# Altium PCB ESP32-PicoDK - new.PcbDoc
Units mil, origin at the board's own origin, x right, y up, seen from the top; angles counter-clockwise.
Board outline 2080 x 1506 mil, 2 copper layers (Top1, Bottom2), stack 40.202 mil thick; 47 components, 68 nets, 274 pads, 137 vias.
Unrouted connection lines stored in the file: 1.
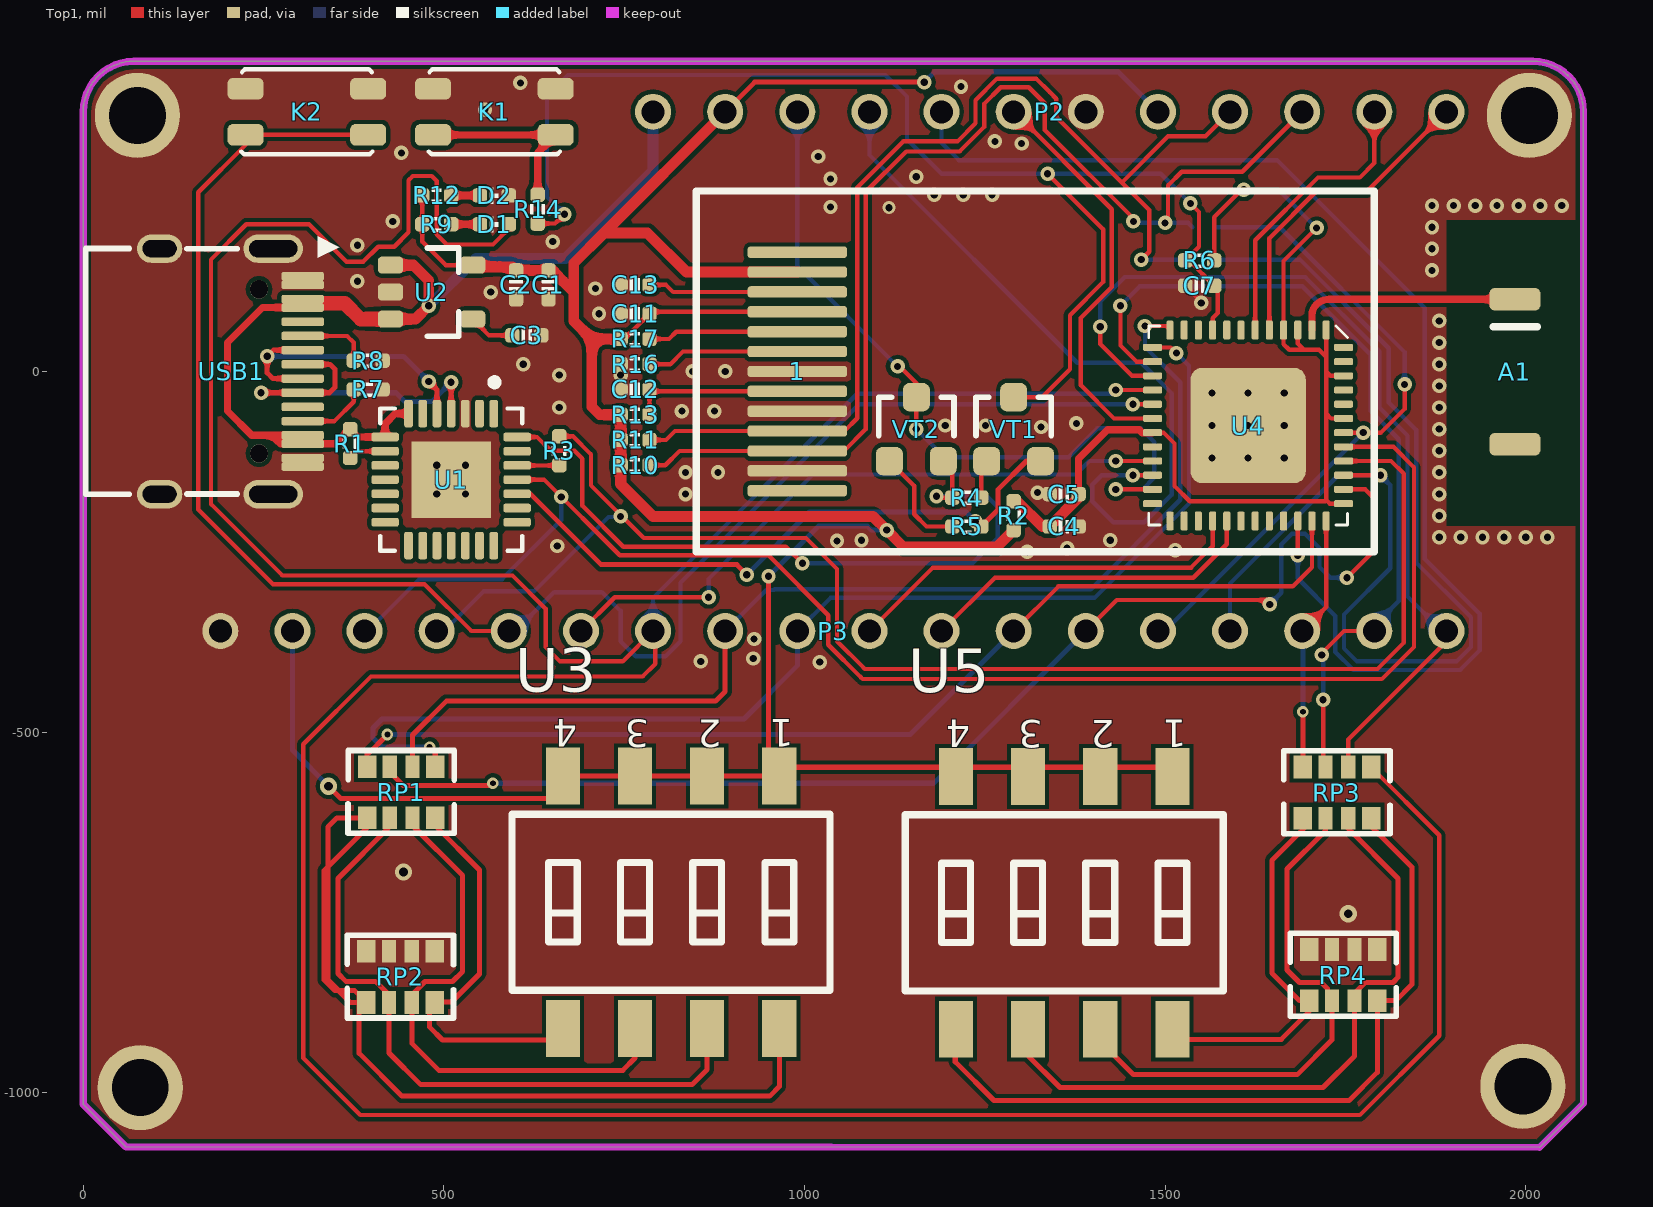
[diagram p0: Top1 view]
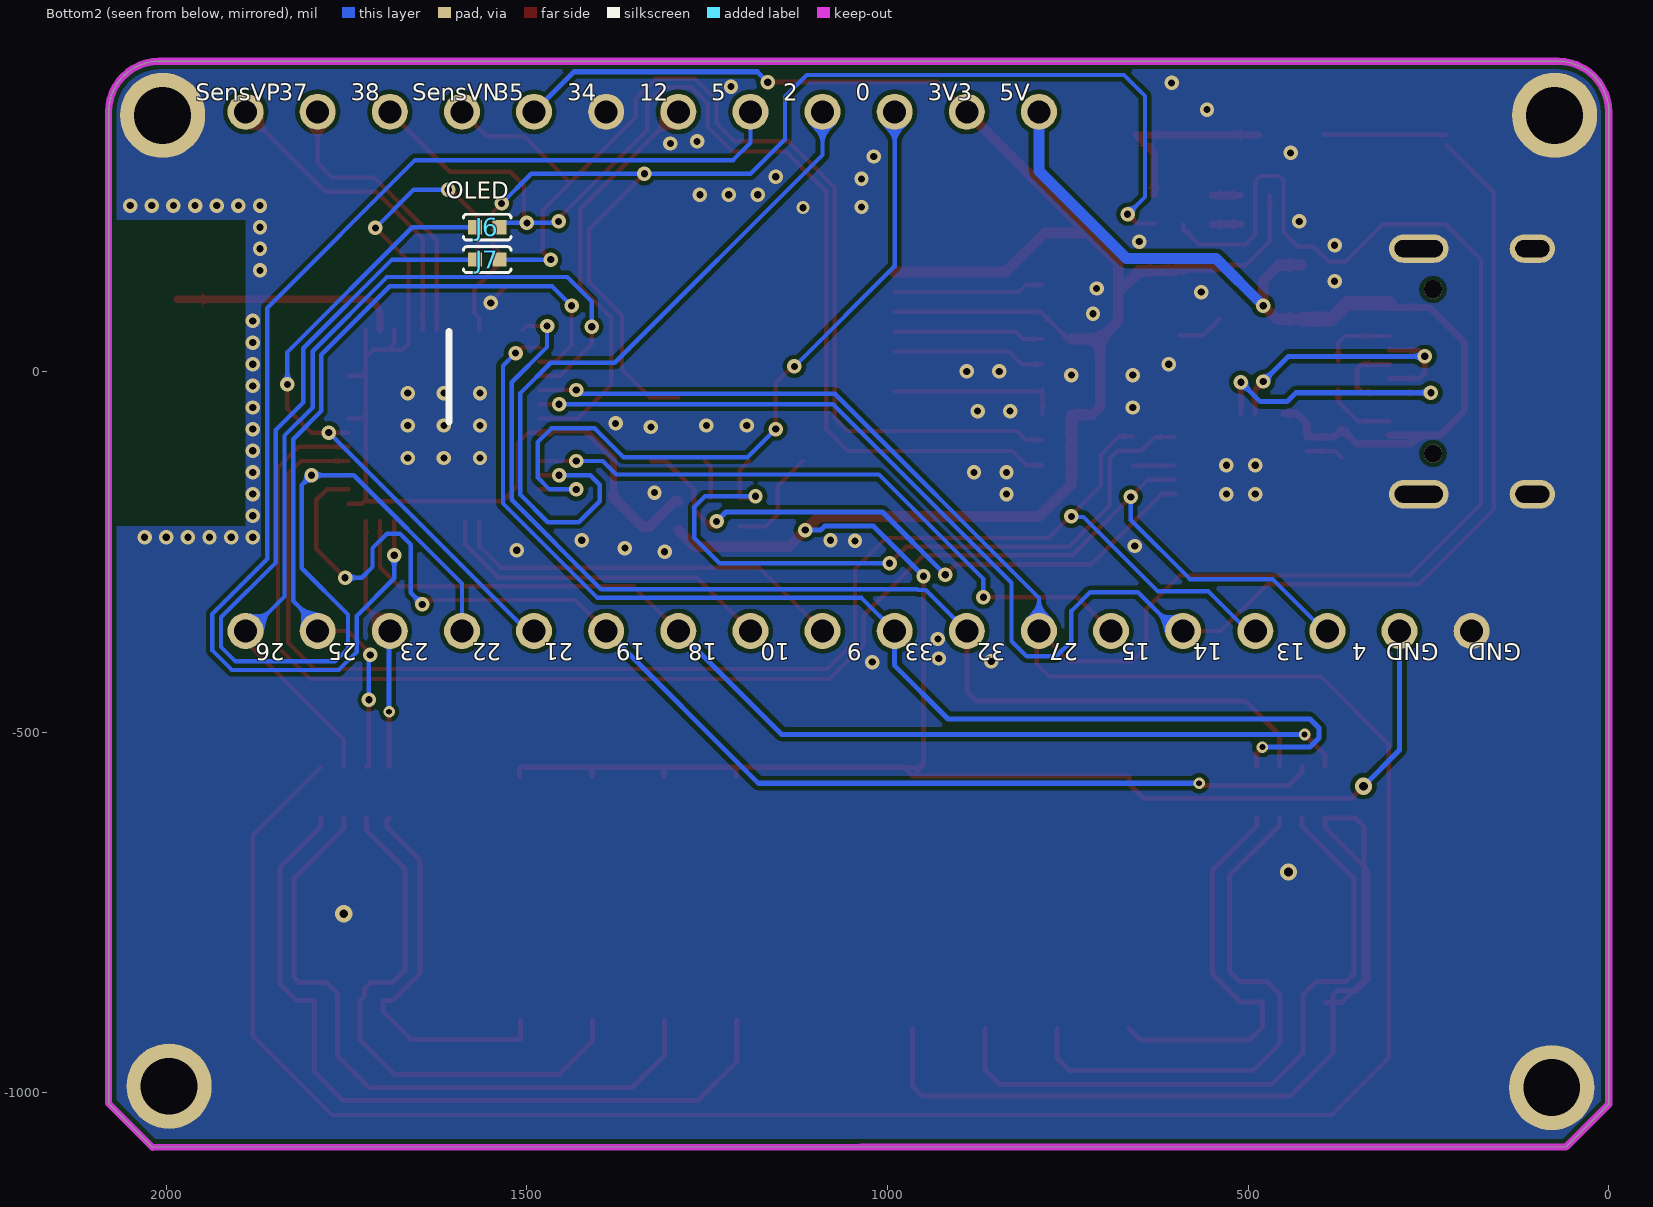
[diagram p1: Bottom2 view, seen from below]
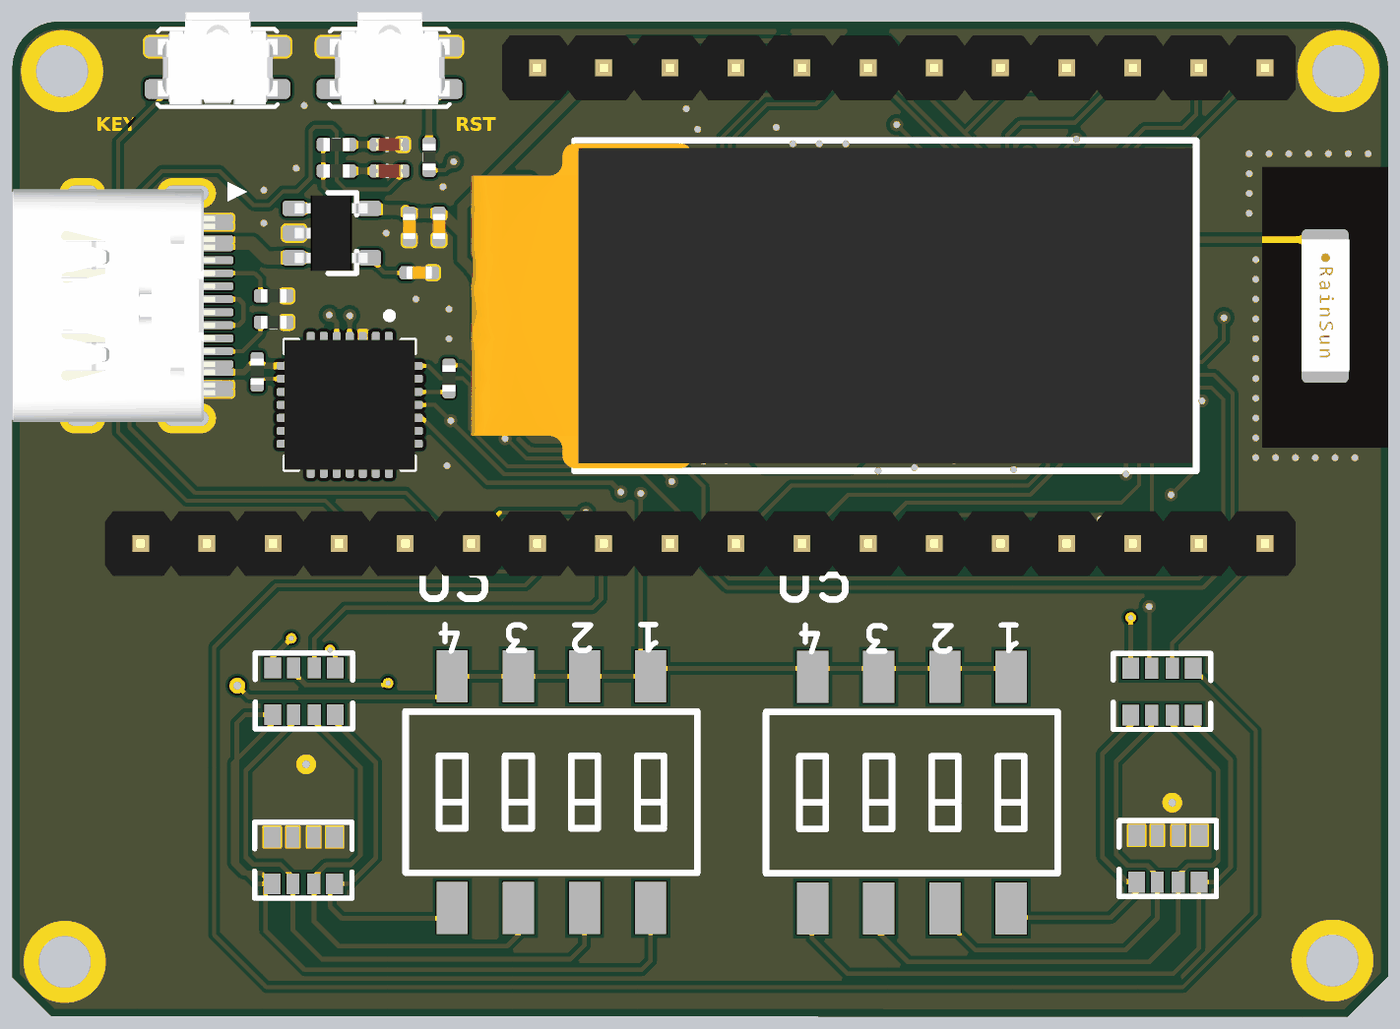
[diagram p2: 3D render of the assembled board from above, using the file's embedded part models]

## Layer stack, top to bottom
Top Solder: solder mask 0.4, Solder Resist, Dk 3.5
Top1: signal copper 1.4
Dielectric 1: core 37.4016, FR-4, Dk 4.2
Bottom2: signal copper 1.4
Bottom Solder: solder mask 0.4, Solder Resist, Dk 3.5

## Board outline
0,-1016 59,-1075 2019,-1076 2080,-1015 2080,360 ccw(c2010,360) 2010,430 70,430 ccw(c70,360) 0,360

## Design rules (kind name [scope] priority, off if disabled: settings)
Clearance [All] p1: gap=6 ignorepadtopadclearanceinfootprint=FALSE
ComponentClearance [All] p1: gap=0 collisioncheckmode=3 verticalgap=0 showdistances=FALSE
DiffPairsRouting [All] p1: maxlimit=9 minlimit=9 mostfreqgap=9 toplayer_minwidth=4 toplayer_maxwidth=4 toplayer_prefwidth=4 bottomlayer_minwidth=4 bottomlayer_maxwidth=4 bottomlayer_prefwidth=4 maxuncoupledlength=500
FanoutControl Fanout_BGA [All] p1: bgadir=Out bgaviamode=Centered fanoutstyle=Auto fanoutdirection=Alternating viagrid=1 // Fanout_BGA (Default Rule)
HoleSize [All] p1: absolutevalues=TRUE maxlimit=10000 minlimit=8 maxpercent=80.000 minpercent=20.000
MinimumSolderMaskSliver [All] p1 off: minsoldermaskwidth=2
PlaneClearance [All] p1: clearance=8
PlaneConnect [All] p1: planeconnectstyle=Direct reliefexpansion=20 reliefentries=4 reliefconductorwidth=10 reliefairgap=10
PolygonConnect [All] p1: connectstyle=Direct reliefconductorwidth=10 reliefentries=4 polygonreliefangle="90 Angle" airgapwidth=10
RoutingVias [All] p1: holewidth=8 width=16 viastyle="Through Hole" minholewidth=6 minwidth=12 maxholewidth=28 maxwidth=50
SilkToBoardRegionClearance [All] p1 off:
SilkToSilkClearance [All] p1: silktosilkclearance=0
SilkToSolderMaskClearance [IsPad] p1: minsilkscreentomaskgap=0 clearancetoexposedcopper=TRUE
SolderMaskExpansion [All] p1: expansion=3
Width [All] p1: maxlimit=10000 minlimit=6 preferedwidth=7
20 further rules are at their usual default settings.

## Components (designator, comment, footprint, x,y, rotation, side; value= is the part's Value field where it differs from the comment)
1 "OLED-12880" OLED-12880 990,0 r180 top locked
A1 "RAINSUN" ANT-Rainsun-AN5120 1985,0 r270 top
C1 "0.1uF" CAP_0402 645,120 r90 top value=0.1u
C2 "10uF" CAP_0402 600,120 r90 top value=0.1u
C3 "10nF" CAP_0402 615,50 r180 top value=0.1u
C4 "10uF" CAP_0402 1360,-215 r180 top value=0.1u
C5 "0.1uF" CAP_0402 1360,-170 r0 top value=0.1u
C7 "0.1uF" CAP_0402 1548,118.89 r180 top value=0.1u
C11 "10uF" CAP_0402 765,80 r0 top value=0.1u
C12 "10uF" CAP_0402 765,-25 r0 top value=0.1u
C13 "10uF" CAP_0402 765,120 r0 top value=0.1u
D1 "color?" LED_0402_RED 570,204 r0 top
D2 "color?" LED_0402_RED 570,244 r0 top
J6 "跳线" 0402-0R 1555,200 r0 bottom
J7 "跳线" 0402-0R 1555,155 r0 bottom
K1 "TACT 4P" ButtonTACT_3.5*3.55_90 570,360 r0 top value=3.4x3.5
K2 "TACT 4P" ButtonTACT_3.5*3.55_90 310,360 r0 top value=3.4x3.5
P2 "HDR1x12_2.54" HDR1X12_2.54_180 1890,360 r270 top locked
P3 "HDR1x18_2.54" HDR1X18_2.54_180 1890,-360 r270 top
R1 "10K" RES_0402 370,-100 r270 top value=22R
R2 "0R" RES_0402 1290,-200 r90 top value=22R
R3 "200R" RES_0402 660,-110 r270 top value=22R
R4 "12K" RES_0402 1225,-175 r0 top value=22R
R5 "12K" RES_0402 1225,-215 r180 top value=22R
R6 "10K" RES_0402 1548,153.89 r180 top value=22R
R7 "5.1K" RES_0402 395,-25 r0 top value=22R
R8 "5.1K" RES_0402 395,15 r0 top value=22R
R9 "1K" RES_0402 490,204 r0 top value=22R
R10 "10K" RES_0402 765,-130 r180 top value=22R
R11 "10K" RES_0402 765,-95 r180 top value=22R
R12 "1K" RES_0402 490,244 r0 top value=22R
R13 "10K" RES_0402 765,-60 r180 top value=22R
R14 "1K" RES_0402 630,225 r270 top value=22R
R16 "560K" RES_0402 765,10 r180 top value=22R
R17 "4.7K" RES_0402 765,45 r180 top value=22R
RP1 "4D03WGJ0102T5E" RES-ARRAY-SMD_0603-8P-L3.2-W1.6-BL 440.75,-583.43 r0 top
RP2 "YC164-JR-075K1L" RES-ARRAY-SMD_0603-8P-L3.2-W1.6-BL 439.75,-839.43 r0 top
RP3 "4D03WGJ0102T5E" RES-ARRAY-SMD_0603-8P-L3.2-W1.6-BL 1738.24,-584 r0 top
RP4 "YC164-JR-075K1L" RES-ARRAY-SMD_0603-8P-L3.2-W1.6-BL 1747,-837 r0 top
U1 "CP2102" QFN-28 510,-150 r270 top value=Value
U2 "LP2992 3V3" SOT23-5 485,110 r0 top
U3 "DM-04-V" SW-SMD_8P-L11.1-W6.2-P2.54-LS9.8 815,-736 r180 top
U4 "ESP32_SIP" QFN-48_7X7 1615,-75 r270 top
U5 "DM-04-V" SW-SMD_8P-L11.1-W6.2-P2.54-LS9.8 1360,-736.81 r180 top
USB1 "Type-C" Type-C-TOP 205,0 r180 top locked
VT1 "S8050" SMT_TRIODE_NPN 1290,-80 r0 top
VT2 "S8050" SMT_TRIODE_NPN 1155,-80 r0 top

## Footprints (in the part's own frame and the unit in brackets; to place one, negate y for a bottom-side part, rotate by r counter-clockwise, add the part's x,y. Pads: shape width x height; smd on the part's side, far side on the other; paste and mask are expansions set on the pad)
0402-0R [mm] "选择焊盘"
  rect 0.5x0.5 smd: 1(-0.432,0) 2(0.432,0)
  silkscreen extent -0.84,-0.46 0.84,0.46
ANT-Rainsun-AN5120 [mm] "选择焊盘"
  rrect50% 0.8x1.8 smd: 1(-2.54,0) ""(2.563,0)
  silkscreen extent -1.57,-0.76 -1.57,0.79, body extent -2.57,-0.91 2.54,0.94, height 1.32
ButtonTACT_3.5*3.55_90 [mil]
  rrect50% 50x30 smd: 1(-85,32) 2(-85,-32) 3(85,32) 4(85,-32)
  silkscreen extent -91,-59 91,59, body extent -90,-55 91,85, height 56
CAP_0402 [mil]
  rrect50% 20x20 smd: 1(-20,0) 2(20,0)
  silkscreen extent -7,-9 7,9, body extent -20,-10 20,10, height 20
HDR1X12_2.54_180 [mil]
  round 50 hole 32: 1(0,0) 2(0,-100) 3(0,-200) 4(0,-300) 5(0,-400) 6(0,-500) 7(0,-600) 8(0,-700) 9(0,-800) 10(0,-900) 11(0,-1000) 12(0,-1100)
  body extent -49,-1150 49,50, height 323
HDR1X18_2.54_180 [mil]
  round 50 hole 32: 1(0,0) 2(0,-100) 3(0,-200) 4(0,-300) 5(0,-400) 6(0,-500) 7(0,-600) 8(0,-700) 9(0,-800) 10(0,-900) 11(0,-1000) 12(0,-1100) 13(0,-1200) 14(0,-1300) 15(0,-1400) 16(0,-1500) 17(0,-1600) 18(0,-1700)
  body extent -49,-1750 49,50, height 323
LED_0402_RED [mil]
  rrect50% 20x20 smd: 1(-20,0) 2(20,0)
  silkscreen extent -6,-11 6,10, body extent -20,-10 20,10, height 18
OLED-12880 [mm]
  rrect50% 3.5x0.4 smd: 1(0,-4.2) 2(0,-3.5) 3(0,-2.8) 4(0,-2.1) 5(0,-1.4) 6(0,-0.7) 7(0,0) 8(0,0.7) 9(0,1.4) 10(0,2.1) 11(0,2.8) 12(0,3.5) 13(0,4.2)
  silkscreen extent -20.32,-6.35 3.56,6.35, body extent -20.18,-6.25 7.54,6.25, height 1.55
QFN-28 [mil]
  rrect50% 38x12 smd mask+5: 1(-91.5,59.05) 2(-91.5,39.37) 3(-91.5,19.68) 4(-91.5,0) 5(-91.5,-19.69) 6(-91.5,-39.37) 7(-91.5,-59.06) 15(91.5,-59.06) 16(91.5,-39.37) 17(91.5,-19.69) 18(91.5,0) 19(91.5,19.68) 20(91.5,39.37) 21(91.5,59.05)
  rrect50% 12x38 smd mask+5: 8(-59.06,-91.5) 9(-39.37,-91.5) 10(-19.69,-91.5) 11(0,-91.5) 12(19.68,-91.5) 13(39.37,-91.5) 14(59.05,-91.5) 22(59.05,91.5) 23(39.37,91.5) 24(19.68,91.5) 25(0,91.5) 26(-19.69,91.5) 27(-39.37,91.5) 28(-59.06,91.5)
  rect 106.3x110.24 smd: 29(0,0)
  silkscreen extent -140,-98 99,99, body extent -99,-99 98,98, height 35
QFN-48_7X7 [mm]
  rrect50% 0.675x0.25 smd: 1(-3.362,2.75) 2(-3.362,2.25) 3(-3.362,1.75) 4(-3.362,1.25) 5(-3.362,0.75) 6(-3.362,0.25) 7(-3.362,-0.25) 8(-3.362,-0.75) 9(-3.362,-1.25) 10(-3.362,-1.75) 11(-3.362,-2.25) 12(-3.362,-2.75) 25(3.363,-2.75) 26(3.363,-2.25) 27(3.363,-1.75) 28(3.363,-1.25) 29(3.363,-0.75) 30(3.363,-0.25) 31(3.363,0.25) 32(3.363,0.75) 33(3.363,1.25) 34(3.363,1.75) 35(3.363,2.25) 36(3.363,2.75)
  rrect50% 0.25x0.675 smd: 13(-2.75,-3.362) 14(-2.25,-3.362) 15(-1.75,-3.362) 16(-1.25,-3.362) 17(-0.75,-3.362) 18(-0.25,-3.362) 19(0.25,-3.362) 20(0.75,-3.362) 21(1.25,-3.362) 22(1.75,-3.362) 23(2.25,-3.362) 24(2.75,-3.362) 37(2.75,3.363) 38(2.25,3.363) 39(1.75,3.363) 40(1.25,3.363) 41(0.75,3.363) 42(0.25,3.363) 43(-0.25,3.363) 44(-0.75,3.363) 45(-1.25,3.363) 46(-1.75,3.363) 47(-2.25,3.363) 48(-2.75,3.363)
  rrect20% 4.064x4.064 smd: 49(0,0)
  silkscreen extent -3.5,-3.5 3.5,3.5, body extent -3.5,-3.5 3.5,3.5, height 1
RES-ARRAY-SMD_0603-8P-L3.2-W1.6-BL [mm]
  rect 0.65x0.8 smd paste+0 mask+0.051: 1(-1.2,-0.9) 4(1.2,-0.9) 5(1.2,0.9) 8(-1.2,0.9)
  rect 0.5x0.8 smd paste+0 mask+0.051: 2(-0.4,-0.9) 3(0.4,-0.9) 6(0.4,0.9) 7(-0.4,0.9)
  silkscreen extent -1.87,-1.45 1.87,1.47
RES_0402 [mil]
  rrect50% 20x20 smd: 1(-20,0) 2(20,0)
  silkscreen extent -7,-10 7,10, body extent -20,-10 20,10, height 14
SMT_TRIODE_NPN [mm] "Surface mount NPN transistor, package SOT-23"
  rrect50% 0.95x1 smd: 1(-0.95,-1.125) 2(0.95,-1.125) 3(0,1.125)
  silkscreen extent -1.33,-0.23 1.32,1.12, body extent -1.45,-1.4 1.45,1.4, height 1.3
SOT23-5 [mm] "SOT23, 3-Leads, Body 3.1x3.0mm (max), Pitch 0.95mm, IPC Medium Density"
  rrect50% 0.889x0.6 smd: 1(-1.5,0.95) 2(-1.5,0) 3(-1.5,-0.95) 4(1.396,-0.95) 5(1.396,0.95)
  silkscreen extent -0.2,-1.55 0.9,1.55, body extent -1.48,-1.45 1.32,1.45, height 1.2
SW-SMD_8P-L11.1-W6.2-P2.54-LS9.8 [mm]
  rect 1.2x2 smd paste+0 mask+0.051: 1(-3.81,-4.45) 2(-1.27,-4.45) 3(1.27,-4.45) 4(3.81,-4.45) 5(3.81,4.45) 6(1.27,4.45) 7(-1.27,4.45) 8(-3.81,4.45)
  silkscreen extent -5.6,-3.1 5.6,3.1
Type-C-TOP [mm]
  round 0.65 hole 0.65: 0(-0.98,2.89) 0(-0.98,-2.89)
  oval 1.6x1 hole 0.6 slot 1.2 at 0 deg: 1(2.52,4.325) 2(2.52,-4.325)
  oval 2.1x1 hole 0.6 slot 1.7 at 0 deg: 3(-1.48,-4.325) 4(-1.48,4.325)
  rrect50% 1.5x0.3 smd: A1(-2.52,-3.35) A4(-2.52,-2.55) A5(-2.52,-1.25) A6(-2.52,-0.25) A7(-2.52,0.25) A8(-2.52,1.25) A9(-2.52,2.55) A12(-2.52,3.35) B1(-2.52,3.05) B4(-2.52,2.25) B5(-2.52,1.75) B6(-2.52,0.75) B7(-2.52,-0.75) B8(-2.52,-1.75) B9(-2.52,-2.25) B12(-2.52,-3.05)
  silkscreen extent -0.22,-4.32 5.12,4.32, body extent -2.57,-4.48 5.18,4.48, height 3.26

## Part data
A1: library part ANT-Rainsun-AP5120
C1 C2 C3 C4 C5 C7 C11 C12 C13: library part 电容-0402, "Capacitor"
D1 D2: library part LED_0402, "LED"
J6 J7: "Resistor"
K1 K2: library part ButtonTACT, "Button"
P2 P3: "Header"
R1 R2 R3 R4 R5 R6 R7 R8 R9 R10 R11 R12 R13 R14 R16 R17: library part 电阻-0402, "Resistor"
RP1 RP2 RP3 RP4: library part RP
U1: "USBתTTL"
U2: library part LP2992, "LDO"
U3 U5: library part "SW DIP-4", "DIP Switch, 4 Position, SPST"
U4: library part ESP32-PICO
USB1: library part USB-Type-C-TOP
VT1 VT2: library part SMT_TRIODE_NPN, "Surface mount NPN transistor, package SOT-23"

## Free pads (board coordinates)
  round 118.11 hole 78.74: ""(75,355) ""(79,-993) ""(1996,-991) ""(2005,355)

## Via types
v1: diameter 20, hole 10, Top1 to Bottom2, tented both sides, 129 vias
v2: diameter 16, hole 8, Top1 to Bottom2, 4 vias
v3: diameter 24, hole 12, Top1 to Bottom2, 3 vias
v4: diameter 18, hole 10, Top1 to Bottom2, tented both sides, 1 vias

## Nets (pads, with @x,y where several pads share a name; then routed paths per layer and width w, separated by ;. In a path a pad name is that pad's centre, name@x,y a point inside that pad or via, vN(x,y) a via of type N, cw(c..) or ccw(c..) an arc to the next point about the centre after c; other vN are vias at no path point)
3V3A: C4.2 C5.2 R2.2 R6.1 U4.1 U4.3 U4.4 U4.19 U4.37 U4.43 U4.46 | length 1444.1
  Top1 w6: U4.19 1497.84,-84.84 1513,-100 1513,-159 1534,-180 1721.53,-180 1723.27,-178.27 ; R6.1 1568,214 1606,252 v1(1609,252) ; U4.3 1683.9,38.74 1692.63,30 ; v1(1710,199) 1664.21,153.21 U4.4 1664.21,37.79 1672,30 1692.63,30 ; U4.1 1723.27,20 ; U4.37 1728.27,-183.27 1723.27,-178.27 ; U4.43 1730.16,-65.16 1723.27,-58.27 ; U4.46 1729.1,-6.1 1723.27,-0.27 ; 1692.63,30 1713.27,30 1723.27,20 ; 1723.27,-178.27 1723.27,-58.27 ; 1723.27,-58.27 1723.27,-0.27 ; 1723.27,-0.27 1723.27,20
  Top1 w7: C4.2@1335,-215 C4.2
  Top1 w10: C5.2 1380,-121 1420,-81 1464,-81 1468,-85 1482.46,-85 U4.19
  Top1 w15: R2.2 1295,-180 1330,-215 C4.2@1335,-215 ; C4.2 1380,-175 C5.2
  Bottom2 w6: v1(1609,252) 1657,252 v1(1710,199)
CP_Rx: P3.16 U1.25 U4.41 | length 2127.6
  Top1 w6: U1.25 638.68,-150 743.68,-255 950,-255 1033,-338 1033,-379 1077.5,-423.5 1077.5,-423.87 1077.87,-423.87 1080.5,-426.5 1800.5,-426.5 1845,-382 1845,-133 1816.53,-104.53 U4.41
  Bottom2 w6: P3.16 394,-360 466,-288 580.73,-288 662.68,-206.06 v1(662.68,-174)
CP_Tx: P3.15 R3.1 U4.40 | length 2049.3
  Top1 w6: R3.1 679,-90 704,-115 704,-158 777,-231 1002,-231 1045,-274 1045,-374.03 1080.98,-410.01 1083.47,-412.5 1794.5,-412.5 1831,-376 1831,-142 1813.21,-124.21 U4.40
  Bottom2 w6: P3.15 491.55,-358.45 501.55,-358.45 555,-305 625,-305 728.13,-201.87 744.13,-201.87 v1(745,-201)
DTR: R4.1 U1.28 VT2.2 | length 1004.8
  Top1 w6: U1.28 628.94,-90.94 648,-110 681,-110 692,-121 692,-186.35 748.65,-243 974,-243 v1(997,-266) ; v1(1183,-173) 1185,-175 R4.1 1205,-136.89 VT2.2
  Bottom2 w6: v1(997,-266) 1233,-266 1268,-231 1268,-188 1253,-173 v1(1183,-173)
EN: C7.1 R6.2 R14.2 U4.9 VT1.3 | length 1857.6
  Top1 w6: R14.2 654,205 v1(667,218) ; VT1.3 1329.29,-35.71 1368,3 1368,78 1414,124 1414,197 v1(1337,274) ; v1(1535,233) 1547,221 1547,172.89 R6.2 1533,153.89 C7.1 1573,113.89 1573,81 1565.79,73.79 U4.9
  Bottom2 w6: v1(667,218) 643,242 643,382 672,411 1112,411 1142,381 1142,322 1190,274 v1(1337,274) 1494,274 v1(1535,233)
FLASH_CLK: U4.31
FLASH_CS: U4.25
FLASH_SD0: U4.27
FLASH_SD1: U4.33
FLASH_SD2: U4.30
FLASH_SD3: U4.32
GND: 1.7 1.9 1.12 C1.1 C2.1 C3.1 C4.1 C5.1 C7.2 C11.1 C12.1 C13.1 D2.2 K1.1 K1.3 K2.1 K2.3 P2.6 P3.18 pad. R7.2 R8.2 R16.2 RP2.5 RP2.6 RP2.7 RP2.8 RP4.5 RP4.6 RP4.7 RP4.8 U1.3 U1.29 U2.2 U4.49 USB1.1 USB1.2 USB1.3 USB1.4 USB1.A1 USB1.A12 USB1.B1 USB1.B12 | length 33
  Top1 w6: C7.2 1550,96.89 v1(1550,95)
  other v1: 1021,-403 856,-402 929,-398 930,-371 1309,-250 1514,-248 1364,-245 657,-242 1045,-235 1079,-234 1424,-234 1880,-230 1910,-230 1940,-230 1970,-230 2000,-230 2030,-230 1880,-200 490,-170 530,-170 835,-170 1880,-170 1323,-168 835,-140 880,-140 1880,-140 490,-130 530,-130 1565,-120 1615,-120 1665,-120 1880,-110 1880,-80 1328,-77 1195,-75 1251,-75 1565,-75 1615,-75 1665,-75 1377,-72 830,-55 875,-55 660,-50 1880,-50 1565,-30 1615,-30 1665,-30 1880,-20 660,-5 745,-5 845,0 890,0 610,10 1880,10 1880,40 1880,70 715,80 565,110 710,115 380,125 1870,140 1870,170 380,175 651,180 1870,200 429,208 1036,228 1870,230 1900,230 1930,230 1960,230 1990,230 2020,230 2050,230 1180,245 1220,245 1260,245 1036,267 1155,270 1019,298 441,303 1301,316 1264,319 557,363 1217,395 606,400
  other v3: 1753.75,-752 444,-694
  other v4: 1117,227
GPIO0: P2.10 U4.23 VT2.3 | length 1041.3
  Top1 w6: v1(1129,7) 1132,7 1155,-16 VT2.3 v1(1155,-80) ; v1(1431.42,-163.58) U4.23
  Bottom2 w6: P2.10 990,146 v1(1129,7) ; v1(1155,-80) 1194,-119 1366,-119 1406,-79 1466,-79 1485,-98 1485,-147 1468.42,-163.58 v1(1431.42,-163.58)
GPIO2: P2.9 U4.22 | length 1006.5
  Top1 w6: v1(1455.27,-143.9) U4.22
  Bottom2 w6: P2.9 1090,300 1378,12 1466.97,12 1509,-30.03 1509,-171 1471,-209 1428,-209 1399,-180 1399,-157 1412.1,-143.9 v1(1455.27,-143.9)
GPIO4: U4.24
GPIO5: P2.8 U4.34 | length 1739
  Top1 w6: v1(1683.9,-254.9) U4.34
  Bottom2 w6: P2.8 1190,317 1214,293 1655,293 1860,88 1860,-260 1936,-336 1936,-386.97 1908.97,-414 1761.03,-414 1736,-388.97 1736,-339 1683.9,-286.9 v1(1683.9,-254.9)
GPIO9: P3.9 U4.28 | length 559.4
  Top1 w6: P3.9 1178,-272 1536.03,-272 1565.79,-242.24 U4.28
GPIO10: P3.8 U4.29 | length 477.5
  Top1 w6: P3.8 1264,-286 1539,-286 1585.47,-239.53 U4.29
GPIO12: P2.7 U4.18 | length 572.5
  Top1 w6: P2.7 1291,360 1426,225 1426,117 1383,74 1383,-19 1429.16,-65.16 U4.18
GPIO13: U4.20
GPIO14: K2.2 K2.4 P3.14 U4.17 | length 2371.7
  Top1 w6: K2.2@225,314 159.48,248.48 159.48,-191.48 263,-295 473.09,-295 538.08,-360 P3.14 ; K2.2 K2.4 ; v1(1455.27,-45.47) U4.17
  Bottom2 w6: P3.14 599,-360 653,-306 718.97,-306 745,-332.03 745,-374 766,-395 807.06,-395 828,-374.06 828,-292.94 1075.47,-45.47 v1(1455.27,-45.47)
GPIO15: P3.13 U4.21 | length 905
  Top1 w6: P3.13 737,-313 v1(867,-313) ; v1(1431.42,-124.21) U4.21
  Bottom2 w6: v1(867,-313) 867,-287.88 1011.88,-143 1375.94,-143 1394.73,-124.21 v1(1431.42,-124.21)
GPIO18: P3.7 RP1.8 U4.35 | length 1498.3
  Top1 w6: P3.7 1352,-298 1677,-298 1703.58,-271.42 U4.35
  Top1 w7: RP1.8 393.51,-531.5 v2(421.63,-503.38)
  Bottom2 w7: v2(421.63,-503.38) 1146.62,-503.38 P3.7
GPIO19: P3.6 RP1.7 U4.38 | length 1746.6
  Top1 w6: P3.6 1433,-317 1639,-317 v1(1645,-323) ; U4.38 1777.58,-163.58 1792,-178 1792,-246 v1(1752,-286)
  Top1 w7: RP1.7 425,-555.53 443.47,-574 565,-574 v2(568,-571)
  Bottom2 w6: v1(1645,-323) 1661,-307 1661,-239.97 1675.97,-225 1694,-225 1714,-245 1714,-271 1729,-286 v1(1752,-286)
  Bottom2 w7: v2(568,-571) 1151.24,-571 1179,-571 P3.6
GPIO21: J6.2 P3.5 U4.42 | length 907.6
  Top1 w6: U4.42 v1(1774.73,-84.84) 1799.16,-84.84 1832,-52 v1(1832,-18)
  Bottom2 w6: P3.5 1499.58,-360 v1(1774.73,-84.84) ; J6.2 1659,200 1832,27 v1(1832,-18)
GPIO22: J7.2 P3.4 U4.39 | length 1602.1
  Top1 w6: U4.39 v1(1798.58,-143.9)
  Bottom2 w6: J7.2 1687.03,155 1810,32.03 1810,-43 1848,-81 1848,-264.97 1924,-340.97 1924,-382 1904,-402 1766,-402 1748,-384 1748,-337 1812,-273 1812,-157.35 v1@1798.58,-143.93 ; P3.4 1590,-294 1740.1,-143.9 v1(1798.58,-143.9)
GPIO23: P3.3 RP3.8 U4.36 | length 355.4
  Top1 w6: P3.3 1723.27,-326.73 U4.36
  Top1 w7: RP3.8 v2(1691,-472)
  Bottom2 w7: P3.3 1691,-361 v2(1691,-472)
GPIO25: P3.2 RP3.7 U4.14 | length 1166.9
  Top1 w6: v1(1438,91) 1438,35.91 1460.33,13.58 U4.14 ; v1@1715.98,-391.98 1747.97,-360 P3.2 ; v1(1719,-455.31) 1719,-548.56 RP3.7
  Bottom2 w6: v1(1438,91) 1465,118 1690.09,118 1785,23.09 1785,-54.97 1824,-93.97 1824,-318.33 1790,-352.33 P3.2 ; v1(1717,-393) 1719,-395 v1(1719,-455.31)
GPIO26: P3.1 RP3.6 U4.15 | length 1268.7
  Top1 w6: v1(1410.03,62.03) 1410,38 1454.1,-6.1 U4.15 ; RP3.6@1753.75,-548.56 1753.75,-510.25 1890,-374 P3.1
  Bottom2 w6: v1(1410.03,62.03) 1410,97 1444,131 1694.06,131 1797,28.06 1797,-50 1836,-89 1836,-312 1884,-360 P3.1
GPIO27: D1.2 P3.12 RP3.5 U4.16 | length 5673.7
  Top1 w6: D1.2 590,198 568,176 504,176 490,190 490,264 483,271 457,271 451,265 451,193 431,173 409,173 388,152 365,152 313,204 226,204 177,155 177,-184 276,-283 595,-283 641,-329 641,-382 661,-402 748,-402 P3.12 793,-363 793,-405.48 775.48,-423 399,-423 305,-517 305,-952 384,-1031 1770,-1031 1880,-921 1880,-643.08 RP3.5 ; v1(1431.42,-25.79) U4.16
  Bottom2 w6: P3.12 790,-313.97 1072.97,-31 1426.2,-31 v1(1431.42,-25.79)
GPIO32: P3.11 RP1.6 U4.12 | length 1591
  Top1 w6: v1(1472,63) 1501.11,63 U4.12
  Top1 w7: RP1.6 456.5,-504.01 503.37,-457.13 876.63,-457.13 890,-443.76 P3.11
  Bottom2 w6: P3.11 947,-303 957.87,-303 958.87,-302 1397.03,-302 1521,-178.03 1521,-15.03 1472,33.97 v1(1472,63)
GPIO33: P3.10 RP1.5 U4.13 | length 1668.4
  Top1 w6: U4.13 1507.73,33.27 v1(1515.58,25.42)
  Top1 w7: v2(480.13,-520.88) 487.99,-528.74 RP1.5
  Bottom2 w6: P3.10 1036,-314 1402,-314 1533,-183 1533,8 v1(1515.58,25.42)
  Bottom2 w7: v2(480.13,-520.88) 414.13,-520.88 401.63,-508.38 401.63,-494.38 414.13,-481.88 916.13,-481.88 990,-408.01 P3.10
GPIO34: U4.10
GPIO35: U4.11
GPIO37: P2.2 U4.6 | length 405
  Top1 w6: U4.6 1624.84,181.87 1711.97,269 1770,269 1790,289 P2.2
GPIO38: U4.7 | length 0.2
  Top1 w6: U4.7@1605,57.54 U4.7
Net1_3: 1.3 C13.2 | length 209
  Top1 w6: C13.2 808,120 817.76,110.24 1.3
Net1_5: 1.5 R17.1 | length 209.2
  Top1 w6: R17.1 812,45 822.12,55.12 1.5
Net1_6: 1.6 R16.1 | length 212.3
  Top1 w6: R16.1 814,10 831.56,27.56 1.6
Net1_8: 1.8 C12.2 R13.1 | length 241.1
  Top1 w6: R13.1 C12.2 787.56,-27.56 1.8
NetA1_1: A1.1 U4.2 | length 422.5
  Top1 w10: U4.2 1703.58,78.09 ; A1.1 1727.66,100 ; 1703.58,78.09 cw(c1723.96,78.09) 1709.55,92.5 ; 1703.58,78.09 cw(c1723.96,78.09) 1709.55,92.5 ; 1703.58,78.09 cw(c1723.96,78.09) 1709.55,92.5 ; 1703.58,78.09 cw(c1723.96,78.09) 1709.55,92.5 ; 1709.55,92.5 cw(c1727.66,74.39) 1727.66,100 ; 1709.55,92.5 cw(c1727.66,74.39) 1727.66,100 ; 1709.55,92.5 cw(c1727.66,74.39) 1727.66,100 ; 1709.55,92.5 cw(c1727.66,74.39) 1727.66,100
NetC3_2: C3.2 U2.4 | length 64.4
  Top1 w6: U2.4 562.54,50 C3.2
NetD1_1: D1.1 R9.2 | length 40
  Top1 w10: R9.2 D1.1
NetD2_1: D2.1 R12.2 | length 40
  Top1 w10: R12.2 D2.1
NetK1_2: K1.2 K1.4 R14.1 | length 263.4
  Top1 w10: K1.2 K1.4 630,303 R14.1
NetR1_2: R1.2 U1.9 | length 52.4
  Top1 w6: R1.2 379.37,-110.63 U1.9
NetR3_2: R3.2 U1.26 | length 58.2
  Top1 w6: U1.26 R3.2@659.68,-130.31
NetR4_2: R4.2 VT1.1 | length 53.9
  Top1 w6: R4.2 1245,-131.89 VT1.1
NetR5_2: R5.2 VT2.1 | length 148
  Top1 w6: VT2.1 1152,-158.69 1152,-198 1169,-215 R5.2
NetR7_1: R7.1 USB1.B5 | length 98.9
  Top1 w6: USB1.B5 348.1,-68.9 375,-42 R7.1
NetR8_1: R8.1 USB1.A5 | length 99.6
  Top1 w6: USB1.A5 365.79,49.21 375,40 R8.1
NetRP1_1: RP1.1 RP2.1 U3.8 | length 1418.6
  Top1 w7: RP2.1 370.12,-874.87 339.13,-843.88 339.13,-631.37 351.63,-618.87 RP1.1 393.51,-632.49 334,-692 334,-843.67 348.95,-858.61 376.24,-858.61 382.51,-864.88 382.51,-945.51 441.88,-1004.88 951.63,-1004.88 965,-991.51 U3.8
NetRP1_2: RP1.2 RP2.2 U3.7 | length 934.2
  Top1 w7: RP1.2 425,-631 353,-703 353,-834.67 363.95,-845.61 405.23,-845.61 424,-864.38 RP2.2 424,-945 468,-989 843.88,-989 865,-967.88 U3.7
NetRP1_3: RP1.3 RP2.3 U3.6 | length 765.4
  Top1 w7: RP1.3 456.5,-629.5 526,-699 526,-832 512,-846 473.88,-846 456,-863.88 456,-932 493,-969 748,-969 765,-952 U3.6
NetRP1_4: RP1.4 RP2.4 U3.5 | length 594.1
  Top1 w7: RP2.4@480.24,-874.44 480.24,-909.24 ; RP1.4 487.99,-629.99 549.37,-691.37 549.37,-835.63 510.56,-874.44 482.91,-874.44 482.91,-877.1 480.24,-879.77 480.24,-909.24 ; U3.5 649.19,-927 498,-927 480.24,-909.24
NetRP3_1: RP3.1 RP4.1 U5.8 | length 550.7
  Top1 w7: U5.8@1509,-899.19 1509,-926 1661,-926 1699.76,-887.24 RP4.1 1686.43,-872.43 1648,-834 1648,-678 1693.62,-632.38 1693.62,-622.06 RP3.1
NetRP3_2: RP3.2 RP4.2 U5.7 | length 763.5
  Top1 w7: U5.7@1409,-899.19 1409,-928 1456,-975 1683,-975 1731.25,-926.75 RP4.2 1724.91,-866.09 1724.91,-855.6 1716.49,-847.19 1686.19,-847.19 1669,-830 1669,-690 1722.25,-636.75 1722.25,-619.67 RP3.2
NetRP3_3: RP3.3 RP4.3 U5.6 | length 945.2
  Top1 w7: U5.6@1309,-899.19 1309,-947.88 1354.12,-993 1719,-993 1762.75,-949.25 RP4.3 1762.75,-861.95 1777.51,-847.19 1815.81,-847.19 1823,-840 1823,-703 1753.75,-633.75 1753.75,-619.67 RP3.3
NetRP3_4: RP3.4 RP4.4 U5.5 | length 1092.2
  Top1 w7: U5.5@1209,-899.19 1209,-957.25 1262.75,-1011 1755.12,-1011 1794.24,-971.88 RP4.4 1819.56,-872.43 1842,-850 1842,-687 1785.48,-630.48 RP3.4
OLED_SCL: 1.10 J7.1 P2.4 R11.1 | length 1532
  Top1 w6: R11.1 808,-95 820.33,-82.67 1.10 1055.33,-82.67 1073,-65 1073,255 1137,319 1212.03,319 1237,343.97 1237,375.97 1267.03,406 1321.14,406 1340.17,386.97 1349,378.14 1349,352.92 1478,223.92 1478,166 v1(1467,155) ; 1440,261.92 1504.08,326 1556,326 P2.4
  Bottom2 w6: v1(1467,155) J7.1
OLED_SDA: 1.11 J6.1 P2.3 R10.1 | length 1564
  Top1 w6: R10.1 807,-130 826.77,-110.23 1.11 1054.77,-110.23 1085,-80 1085,249 1141,305 1215,305 1249,339 1249,371 1272,394 1311,394 1333.14,371.86 1333.14,334.86 v1@1458.87,209.13 ; v1(1500,206) 1500,207.19 1504,211.19 1504,258 1523,277 1607,277 P2.3
  Bottom2 w6: v1@1459.38,206.37 1459.38,206 1532,206 J6.1
  other v1: 1456,208
RTS: R5.1 U1.24 VT1.2 | length 874.3
  Top1 w7: U1.24 619.68,-169.68 718,-268 906,-268 v1(920,-282) ; v1(1237,-208) 1237.88,-208.88 1237.88,-215 R5.1 1268,-192 1268,-164 1307.71,-124.29 VT1.2
  Bottom2 w7: v1(920,-282) 1007,-195 1224,-195 v1(1237,-208)
SENSOR_VN: U4.8
SENSOR_VP: P2.1 U4.5 | length 445.3
  Top1 w6: U4.5 1644.53,184.59 1708.94,249 1779,249 P2.1
USB-PWR-DM: U1.5 USB1.A7 USB1.B7 | length 415.9
  Top1 w7: USB1.A7 262.84,-9.84 255,-2 v1(255,21) 263.53,29.53 USB1.B7 ; v1(479,-14) 490.31,-25.31 U1.5
  Bottom2 w7: v1(255,21) 444,21 v1(479,-14)
USB-PWR-DP: U1.4 USB1.A6 USB1.B6 | length 501.5
  Top1 w7: v1(246.53,-29.53) USB1.B6 341.47,-29.53 349,-22 349,3 342.16,9.84 USB1.A6 ; U1.4 v1(510,-15)
  Bottom2 w7: v1(246.53,-29.53) 433.53,-29.53 445.91,-41.91 483.09,-41.91 v1(510,-15)
VBUS: P2.12 R1.1 U1.7 U1.8 U2.1 U2.3 USB1.A4 USB1.A9 USB1.B4 USB1.B9 | length 1339.2
  Top1 w7: USB1.B9 304.21,94.58 USB1.A4
  Top1 w10: USB1.B4 262,-88.58 ; USB1.B9 248.58,88.58 200,40 200,-55 233.58,-88.58 262,-88.58 ; U1.7 432.5,-58.5 418.5,-72.5 U1.8 380.94,-90.94 R1.1 349.61,-100.39 USB1.A9 273.81,-100.39 262,-88.58
  Top1 w15: U2.3 460.6,72.6 v1(479,91) 479,126 457.6,147.4 U2.1
  Top1 w20: USB1.A4@304.21,94.58 362.42,94.58 384.4,72.6 U2.3
  Bottom2 w15: v1(479,91) 544.5,156.5 668.5,156.5 790,278 P2.12
VCC_3V3: 1.2 1.4 C1.2 C2.2 C11.2 P2.5 P2.11 P3.17 R2.1 R9.1 R10.2 R11.2 R12.1 R13.2 R17.2 U2.5 U3.1 U3.2 U3.3 U3.4 U5.1 U5.2 U5.3 U5.4 | length 5670.4
  Top1 w6: R12.1 R9.1 470,180 502.6,147.4 U2.5 ; R17.2 750,45 C11.2 787.68,82.68 1.4
  Top1 w7: v3(340,-575) 357,-592 644.88,-592 665,-571.88 U3.4 U3.3 U3.2 U3.1 ; P2.11 931,401 v1(1166,401) ; U5.4 U5.4@1210,-548.88 ; U5.3 U5.3@1310,-548.88 ; U5.2 U5.2@1410,-548.88 ; U5.1 1510,-548.88 U5.2@1410,-548.88 ; U3.1 950,-545.81 v1(950,-284) 953,-284 955,-286 951.13,-286 950.13,-287 950.13,-541.88 957.13,-548.88 U5.4@1210,-548.88 ; U3.1 977,-548.81 1309,-548.81 1410,-548.81 1509,-548.81 U5.2@1410,-548.88 ; U5.4@1210,-548.88 U5.3@1310,-548.88 ; U5.3@1310,-548.88 U5.2@1410,-548.88
  Top1 w15: U2.5 542.35,145 595,145 C2.2 C1.2 650,140 680,110 ; R17.2 705,45 ; P2.11 722,192 ; 1.2 836.2,137.8 782,192 722,192 ; R2.1 1267,-243 1137,-243 v1(1114,-220) 1095,-201 790,-201 745,-156 R10.2 R11.2 R13.2 716,-60 705,-49 705,45 ; 680,110 680,150 722,192 ; 680,110 680,70 705,45
  Bottom2 w7: P3.17 290,-525 v3(340,-575) ; v1(950,-284) 1019.5,-214.5 1087.08,-214.5 1092.58,-220 v1(1114,-220) ; v1(1166,401) 1180.5,415.5 1434.5,415.5 P2.5
pads on no net: 1.1 1.13 A1. U1.1 U1.2 U1.6 U1.10 U1.11 U1.12 U1.13 U1.14 U1.15 U1.16 U1.17 U1.18 U1.19 U1.20 U1.21 U1.22 U1.23 U1.27 U4.26 U4.44 U4.45 U4.47 U4.48 USB1.0 USB1.A8 USB1.B8

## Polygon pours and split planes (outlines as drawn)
GND on Bottom2 "GND_L02_P001" (solid, remove dead copper, pour order 1): -21.12,449.13 -21.12,-1074.96 2098.88,-1075 2098.88,449.13
GND on Top1 "GND_L01_P000" (solid, remove dead copper, pour order 0): -20,460 -20,-1076.03 2080,-1076.03 2100,460

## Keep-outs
Keep-Out Layer:
  the board outline again, w10

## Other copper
Top1:
  pour cut-out: 1890,210 1890,-215 2115,-215 2115,210
Bottom2:
  pour cut-out: 1890,210 1890,-215 2115,-215 2115,210

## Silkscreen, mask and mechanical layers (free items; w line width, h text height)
Top Overlay:
  region: 325,157.5 325,187.5 355,172.5
Bottom Overlay:
  lines w10: 1607.84,-69.84 1607.84,55.16
  text "5V" at 844.24,367.98 h40
  text "3V3" at 944.24,367.98 h40
  text "0" at 1044.24,367.98 h40
  text "2" at 1144.24,367.98 h40
  text "5" at 1244.24,367.98 h40
  text "12" at 1344.24,367.98 h40
  text "34" at 1444.24,367.98 h40
  text "35" at 1544.24,367.98 h40
  text "SensVN" at 1659.09,367.98 h40
  text "38" at 1744.24,367.98 h40
  text "37" at 1844.24,367.98 h40
  text "SensVP" at 1959.09,367.98 h40
  text "OLED" at 1612.58,232.01 h40
  text "GND" at 120.91,-368.98 h40 r180
  text "GND" at 235.76,-368.98 h40 r180
  text "4" at 335.76,-368.98 h40 r180
  text "13" at 420.91,-368.98 h40 r180
  text "14" at 535.76,-368.98 h40 r180
  text "15" at 635.76,-368.98 h40 r180
  text "27" at 735.76,-368.98 h40 r180
  text "32" at 835.76,-368.98 h40 r180
  text "33" at 935.76,-368.98 h40 r180
  text "9" at 1035.76,-368.98 h40 r180
  text "10" at 1135.76,-368.98 h40 r180
  text "18" at 1235.76,-368.98 h40 r180
  text "19" at 1335.76,-368.98 h40 r180
  text "21" at 1435.76,-368.98 h40 r180
  text "22" at 1535.76,-368.98 h40 r180
  text "23" at 1635.76,-368.98 h40 r180
  text "25" at 1735.76,-368.98 h40 r180
  text "26" at 1835.76,-368.98 h40 r180
Top Solder:
  rectangle: 1890,-215 2115,210
  text "KEY" at 118.18,236.99 h40
  text "RST" at 661.65,236.99 h40
Bottom Solder:
  rectangle: 1890,-215 2115,210
Mechanical 1:
  lines w10: 0,-360 0,360 cw(c70,360) 70,430 2010,430 cw(c2010,360) 2080,360 2080,-1015 2019,-1076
